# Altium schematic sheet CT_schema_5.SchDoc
size 278 x 170 mm
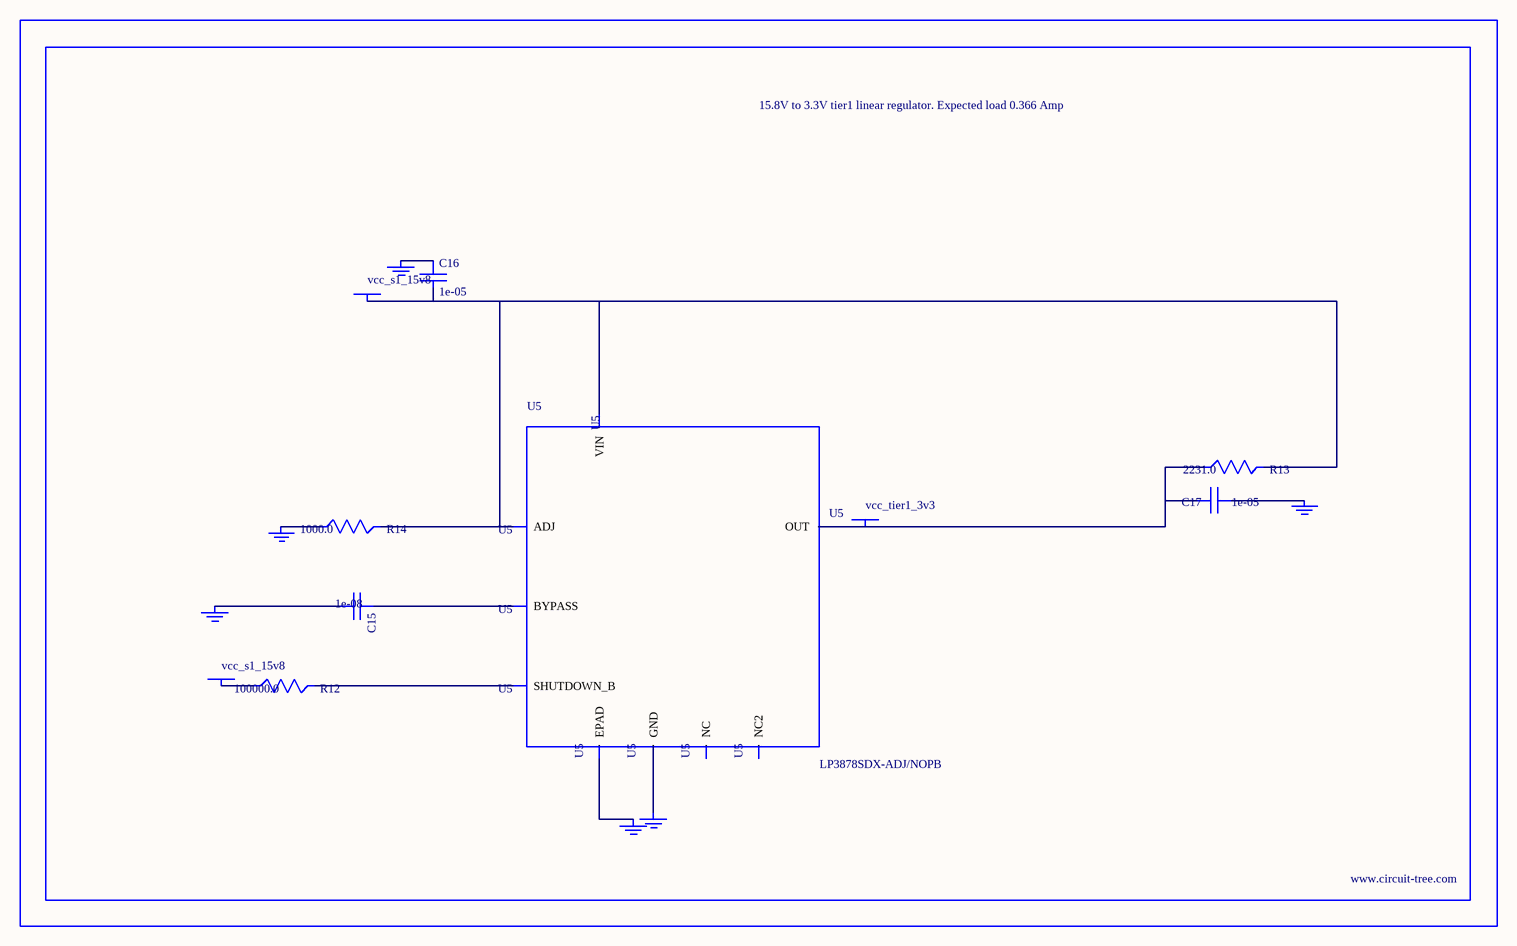
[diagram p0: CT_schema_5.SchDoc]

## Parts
BORDER4  (no value)
C15  1e-08  [C0402]
C16  1e-05  [C1210]
C17  1e-05  [C1210]
GND_INSTANCE_4_0  (no value)
GND_INSTANCE_4_1  (no value)
GND_INSTANCE_4_2  (no value)
GND_INSTANCE_4_3  (no value)
GND_INSTANCE_4_4  (no value)
GND_INSTANCE_4_5  (no value)
POWER_INSTANCE_4_0  vcc_s1_15v8
POWER_INSTANCE_4_1  vcc_s1_15v8
POWER_INSTANCE_4_2  vcc_tier1_3v3
R12  100000.0  [R0603]
R13  2231.0  [R0603]
R14  1000.0  [R0603]
U5  LP3878SDX-ADJ/NOPB  [WSON-8]

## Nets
NetC15_1: C15.1 U5.1(BYPASS)
NetC15_2: C15.2 GND_INSTANCE_4_0.0(GND)
NetC16_1: C16.1 GND_INSTANCE_4_1.0(GND)
NetC16_2: C16.2 POWER_INSTANCE_4_0.0(PWR) R13.2 R14.2 U5.4(VIN) U5.6(ADJ)
NetC17_1: C17.1 GND_INSTANCE_4_2.0(GND)
NetC17_2: C17.2 POWER_INSTANCE_4_2.0(PWR) R13.1 U5.5(OUT)
NetGND_INSTANCE_4_3_0: GND_INSTANCE_4_3.0(GND) R14.1
NetGND_INSTANCE_4_4_0: GND_INSTANCE_4_4.0(GND) U5.PAD(EPAD)
NetGND_INSTANCE_4_5_0: GND_INSTANCE_4_5.0(GND) U5.3(GND)
NetPOWER_INSTANCE_4_1_0: POWER_INSTANCE_4_1.0(PWR) R12.1
NetR12_2: R12.2 U5.8(SHUTDOWN_B)

Not connected (* = marked no-connect by the designer): U5 2(NC) 7(NC2)

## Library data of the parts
BORDER4 = BORDER_PAGE4
C15 = C0402C103K3RAC
C16 = C1210C106K5PACTU
C17 = GRM32DR61E106MA12L
GND_INSTANCE_4_0-GND_INSTANCE_4_5 = GND
POWER_INSTANCE_4_0-POWER_INSTANCE_4_2 = PWR
R12 = RC0603JR-07100KL
R13 = R13
R14 = RC0603JR-071KL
